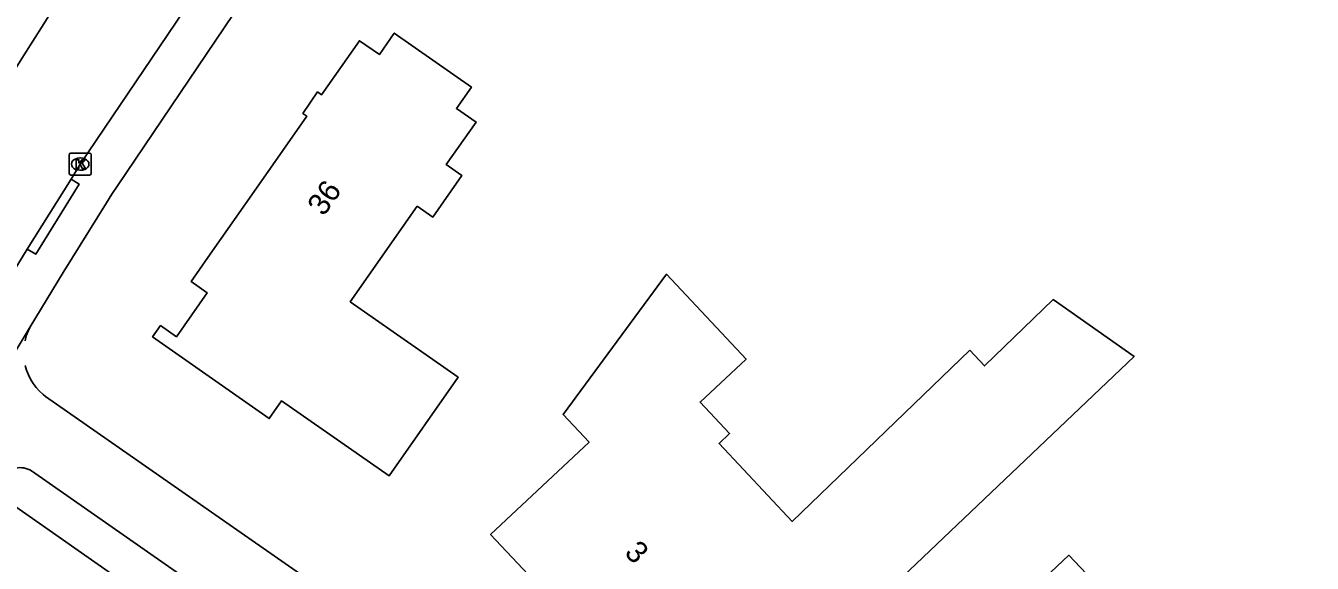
# Model space of a CAD drawing. Extents: x 158838 to 160074, y 386376 to 387776.
# Drawn here: x 159315.9 to 159374.7, y 386761.9 to 386786.4 of the extents above; entities that cross this region are included whole.
import ezdxf

# ---------------------------------------------------------------- set-up
doc = ezdxf.new("R2010")
doc.units = 0
for name, color, linetype in [('IMGEO_Kolk', 7, 'Continuous'), ('IMGEO_Pand', 7, 'Continuous'), ('IMGEO_Pand_nummerreeks', 7, 'Continuous'), ('IMGEO_Rijbaan_lokaal_gesloten', 7, 'Continuous'), ('IMGEO_Rijbaan_lokaal_open', 7, 'Continuous'), ('IMGEO_Voetpad_open', 7, 'Continuous')]:
    doc.layers.add(name, color=color, linetype=linetype)

msp = doc.modelspace()

# ---------------------------------------------------------------- linework, layer by layer
at = {"layer": 'IMGEO_Kolk'}
for p, q in [((159317.911, 386779.65), (159317.911, 386780.502)), ((159317.986, 386780.576), (159318.838, 386780.576)), ((159318.912, 386780.502), (159318.912, 386779.65)), ((159318.422, 386779.796), (159318.397, 386779.796)), ((159318.399, 386780.356), (159318.424, 386780.356)), ((159318.838, 386779.576), (159317.986, 386779.576))]:
    msp.add_line(p, q, dxfattribs=at)
for points in [[(159317.911, 386779.65), (159317.911, 386780.502)], [(159317.986, 386780.576), (159318.838, 386780.576)], [(159318.912, 386780.502), (159318.912, 386779.65)], [(159318.232, 386780.276), (159318.355, 386780.276), (159318.355, 386780.125), (159318.485, 386780.276), (159318.649, 386780.276), (159318.503, 386780.125), (159318.656, 386779.876), (159318.504, 386779.876), (159318.419, 386780.04), (159318.355, 386779.973), (159318.355, 386779.876), (159318.232, 386779.876), (159318.232, 386780.276)], [(159318.838, 386779.576), (159317.986, 386779.576)]]:
    msp.add_lwpolyline(points, dxfattribs=at)
for centre, start, end in [((159317.988, 386780.5), 91.55205, 178.44795), ((159317.988, 386780.5), 91.55205, 178.44795), ((159318.836, 386780.5), 1.55205, 88.44795), ((159318.836, 386780.5), 1.55205, 88.44795), ((159317.988, 386779.652), 181.55205, 268.44795), ((159317.988, 386779.652), 181.55205, 268.44795), ((159318.836, 386779.652), 271.55205, 358.44795), ((159318.836, 386779.652), 271.55205, 358.44795)]:
    msp.add_arc(centre, 0.0765, start, end, dxfattribs=at)
for centre, major_axis, ratio, start_param, end_param in [((159318.398, 386780.076), (-0.387, 0.002), 0.722429, 4.712389, 7.853982), ((159318.423, 386780.076), (-0.39, 0.002), 0.717154, 1.570796, 4.712389)]:
    msp.add_ellipse(centre, major_axis=major_axis, ratio=ratio, start_param=start_param, end_param=end_param, dxfattribs=at)
at = {"layer": 'IMGEO_Pand'}
for points in [[(159333.795, 386778.153), (159334.509, 386777.653), (159335.839, 386779.554), (159335.125, 386780.055), (159336.481, 386781.994), (159335.585, 386782.615), (159336.268, 386783.589), (159332.747, 386786.057), (159332.073, 386785.074), (159331.16, 386785.707), (159329.432, 386783.243), (159329.251, 386783.368), (159328.577, 386782.39), (159328.752, 386782.258), (159326.562, 386779.131), (159324.242, 386775.818), (159323.472, 386774.719), (159324.209, 386774.196), (159322.807, 386772.192), (159322.08, 386772.706), (159321.716, 386772.191), (159327.039, 386768.46), (159327.607, 386769.271), (159332.513, 386765.84), (159335.666, 386770.347), (159330.743, 386773.79), (159333.795, 386778.153)], [(159359.023, 386771.574), (159359.699, 386770.864), (159362.834, 386773.887), (159366.518, 386771.296), (159350.668, 386756.203), (159349.626, 386757.297), (159349.219, 386756.918), (159348.912, 386757.237), (159348.611, 386757.55), (159345.646, 386754.756), (159341.747, 386758.911), (159342.388, 386759.513), (159340.785, 386761.179), (159339.848, 386760.287), (159337.146, 386763.161), (159341.641, 386767.387), (159340.456, 386768.648), (159345.169, 386775.05), (159348.806, 386771.172), (159346.713, 386769.209), (159348.058, 386767.775), (159347.575, 386767.322), (159350.917, 386763.758), (159359.023, 386771.574)], [(159354.389, 386753.591), (159357.652, 386750.124), (159359.172, 386751.55), (159355.904, 386755.011), (159363.54, 386762.218), (159368.072, 386757.42), (159369.305, 386758.55), (159374.302, 386750.47), (159373.542, 386750), (159365.38, 386744.952), (159364.003, 386746.416), (159362.584, 386747.923), (159360.977, 386746.4), (159356.973, 386742.653), (159350.3, 386749.743), (159350.573, 386750), (159354.389, 386753.591)]]:
    msp.add_lwpolyline(points, dxfattribs=at)
at = {"layer": 'IMGEO_Rijbaan_lokaal_gesloten'}
for points in [[(159338.584, 386808.987), (159337.228, 386807.215), (159331.144, 386798.935), (159318.41, 386780.077), (159317.993, 386779.394)], [(159315.986, 386776.187), (159317.993, 386779.394)], [(159315.986, 386776.187), (159312.283, 386770.118)]]:
    msp.add_lwpolyline(points, dxfattribs=at)
msp.add_arc((160125.957, 386272.494), 958.644, 147.182569, 148.985825, dxfattribs=at)
at = {"layer": 'IMGEO_Rijbaan_lokaal_open'}
msp.add_lwpolyline([(159313.064, 386766.095), (159329.132, 386754.848)], dxfattribs=at)
at = {"layer": 'IMGEO_Voetpad_open'}
for points in [[(159316.126, 386772.648), (159317.633, 386775.122), (159319.614, 386778.311), (159319.861, 386778.699), (159320.11, 386779.086), (159332.731, 386797.78), (159338.763, 386805.976), (159342.557, 386810.947), (159349.576, 386819.722), (159352.408, 386823.136), (159354.876, 386826.001), (159357.532, 386829.072), (159359.977, 386831.86), (159360.256, 386832.178), (159367.963, 386840.464), (159376.841, 386849.467), (159376.759, 386849.577), (159385.976, 386858.576)], [(159317.993, 386779.394), (159318.358, 386779.165), (159316.38, 386775.963), (159315.986, 386776.187)], [(159312.466, 386766.552), (159316.126, 386772.648)], [(159315.895, 386772.01), (159315.953, 386772.23), (159316.03, 386772.443), (159316.126, 386772.648)], [(159353.036, 386730.878), (159355.284, 386732.311), (159348.514, 386743.258), (159344.722, 386748.625), (159343.45, 386750), (159340.839, 386752.463), (159338.018, 386754.682), (159337.812, 386754.829), (159335.344, 386756.558), (159316.823, 386769.467), (159316.718, 386769.553), (159316.553, 386769.708), (159316.403, 386769.878), (159316.268, 386770.06), (159316.15, 386770.254), (159316.05, 386770.457), (159315.968, 386770.668), (159315.906, 386770.886)], [(159313.064, 386766.095), (159313.228, 386766.022), (159313.399, 386765.964), (159313.573, 386765.921), (159313.751, 386765.894), (159313.931, 386765.883), (159314.111, 386765.888), (159314.289, 386765.91), (159314.434, 386765.939), (159315.406, 386766.184), (159315.473, 386766.199), (159315.564, 386766.212), (159315.657, 386766.217), (159315.75, 386766.213), (159315.842, 386766.202), (159315.933, 386766.182), (159316.021, 386766.154), (159316.107, 386766.118), (159316.189, 386766.075), (159330.158, 386756.317)]]:
    msp.add_lwpolyline(points, dxfattribs=at)
for centre, radius, start, end in [((159664.307, 386559.772), 420.071, 145.86839, 150.94063), ((159674.562, 386553.175), 429.075, 145.91413, 150.83623)]:
    msp.add_arc(centre, radius, start, end, dxfattribs=at)

# ---------------------------------------------------------------- texts
at = {"layer": 'IMGEO_Pand_nummerreeks'}
for s, rotation, p in [('36', 55.02114, (159329.53, 386777.655)), ('3', 313.89594, (159343.212, 386762.292))]:
    msp.add_text(s, height=1, rotation=rotation, dxfattribs=at).set_placement(p)

doc.saveas('drawing.dxf')
